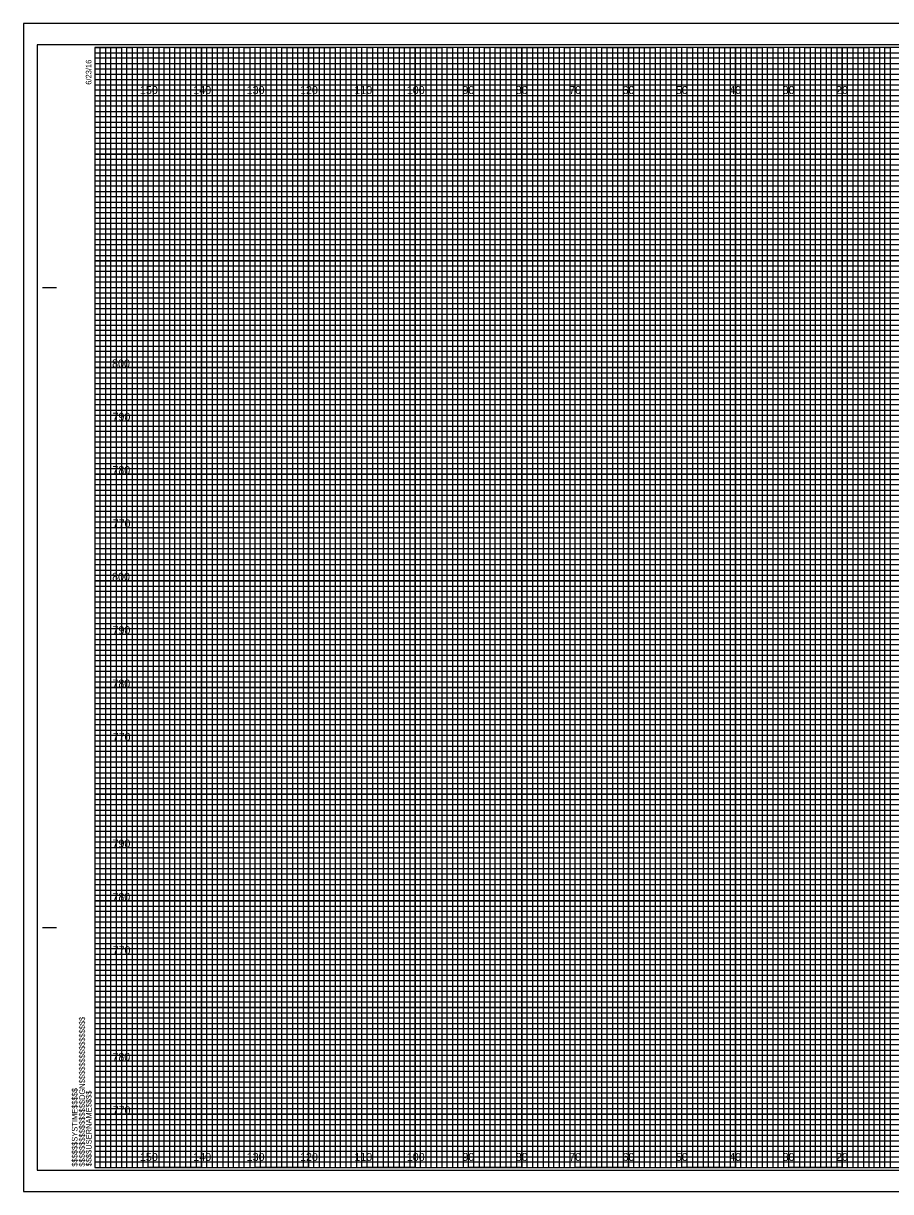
# Model space of a CAD drawing. Extents: x -13 to 323, y -4 to 214.
# Drawn here: x -13.4 to 149.1, y -4.5 to 214.5 of the extents above; entities that cross this region are included whole.
import ezdxf

# ---------------------------------------------------------------- set-up
doc = ezdxf.new("R2010")
doc.units = 0
for name, color, linetype in [('Exist Cross Section Cell', 7, 'Continuous'), ('Exist XS Center Line Elevation Label', 7, 'Continuous'), ('Exist XS Ground Line', 7, 'Continuous'), ('Prop CMT Conc Surface', 7, 'Continuous'), ('Prop CMT Concrete Structures', 7, 'Continuous'), ('Prop CMT Pvmt Course 1', 7, 'Continuous'), ('Prop CMT Pvmt Course 1 CG', 7, 'Continuous'), ('Prop CMT Pvmt Course 2', 7, 'Continuous'), ('Prop CMT Pvmt Surface', 7, 'Continuous'), ('Scratch_Level_1', 7, 'Continuous'), ('Scratch_Level_7', 7, 'Continuous')]:
    doc.layers.add(name, color=color, linetype=linetype)

msp = doc.modelspace()

# ---------------------------------------------------------------- linework, layer by layer
at = {"layer": 'Exist XS Center Line Elevation Label'}
for points in [[(0, 210), (5, 210), (5, 0), (15, 0), (15, 210), (25, 210), (25, 0), (35, 0), (35, 210), (45, 210), (45, 0), (55, 0), (55, 210), (65, 210), (65, 0), (75, 0), (75, 210), (85, 210), (85, 0), (95, 0), (95, 210), (105, 210), (105, 0), (115, 0), (115, 210), (125, 210), (125, 0), (135, 0), (135, 210), (145, 210), (145, 0), (155, 0)], [(0, 205), (275, 205)], [(0, 185), (320, 185), (320, 195), (0, 195)], [(0, 165), (320, 165), (320, 175), (0, 175)], [(0, 145), (320, 145), (320, 155), (0, 155)], [(0, 125), (320, 125), (320, 135), (0, 135)], [(0, 105), (320, 105), (320, 115), (0, 115)], [(0, 85), (320, 85), (320, 95), (0, 95)], [(0, 65), (320, 65), (320, 75), (0, 75)], [(0, 45), (320, 45), (320, 55), (0, 55)], [(0, 25), (320, 25), (320, 35), (0, 35)], [(0, 5), (320, 5), (320, 15), (0, 15)]]:
    msp.add_lwpolyline(points, dxfattribs=at)
at = {"layer": 'Exist XS Ground Line'}
for p, q in [((10, 210), (0, 210)), ((10, 0), (10, 210)), ((30, 210), (20, 210)), ((20, 210), (20, 0)), ((30, 0), (30, 210)), ((50, 210), (40, 210)), ((40, 210), (40, 0)), ((50, 0), (50, 210)), ((70, 210), (60, 210)), ((60, 210), (60, 0)), ((70, 0), (70, 210)), ((90, 210), (80, 210)), ((80, 210), (80, 0)), ((90, 0), (90, 210)), ((110, 210), (100, 210)), ((100, 210), (100, 0)), ((110, 0), (110, 210)), ((130, 210), (120, 210)), ((120, 210), (120, 0)), ((130, 0), (130, 210)), ((150, 210), (140, 210)), ((140, 210), (140, 0)), ((20, 0), (10, 0)), ((40, 0), (30, 0)), ((60, 0), (50, 0)), ((80, 0), (70, 0)), ((100, 0), (90, 0)), ((120, 0), (110, 0)), ((140, 0), (130, 0))]:
    msp.add_line(p, q, dxfattribs=at)
for points in [[(0, 200), (320, 200), (320, 190), (0, 190)], [(0, 180), (320, 180), (320, 170), (0, 170)], [(0, 160), (320, 160), (320, 150), (0, 150)], [(0, 140), (320, 140), (320, 130), (0, 130)], [(0, 120), (320, 120), (320, 110), (0, 110)], [(0, 100), (320, 100), (320, 90), (0, 90)], [(0, 80), (320, 80), (320, 70), (0, 70)], [(0, 60), (320, 60), (320, 50), (0, 50)], [(0, 40), (320, 40), (320, 30), (0, 30)], [(0, 20), (320, 20), (320, 10), (0, 10)]]:
    msp.add_lwpolyline(points, dxfattribs=at)
at = {"layer": 'Prop CMT Concrete Structures'}
msp.add_lwpolyline([(-13.4, -4.5), (323.3, -4.5), (323.3, 214.5), (-13.4, 214.5)], close=True, dxfattribs=at)
at = {"layer": 'Prop CMT Pvmt Course 1'}
for p, q in [((323.3, 214.5), (-13.4, 214.5)), ((-13.4, 214.5), (-13.4, -4.5)), ((-13.4, -4.5), (323.3, -4.5))]:
    msp.add_line(p, q, dxfattribs=at)
at = {"layer": 'Prop CMT Pvmt Course 1 CG'}
for p, q in [((10, 0), (10, 210)), ((20, 0), (20, 210)), ((30, 0), (30, 210)), ((40, 0), (40, 210)), ((50, 0), (50, 210)), ((60, 0), (60, 210)), ((70, 0), (70, 210)), ((80, 0), (80, 210)), ((90, 0), (90, 210)), ((100, 0), (100, 210)), ((110, 0), (110, 210)), ((120, 0), (120, 210)), ((130, 0), (130, 210)), ((140, 0), (140, 210)), ((0, 200), (320, 200)), ((0, 190), (320, 190)), ((0, 180), (320, 180)), ((0, 170), (320, 170)), ((0, 160), (320, 160)), ((0, 150), (320, 150)), ((0, 140), (320, 140)), ((0, 130), (320, 130)), ((0, 120), (320, 120)), ((0, 110), (320, 110)), ((0, 100), (320, 100)), ((0, 90), (320, 90)), ((0, 80), (320, 80)), ((0, 70), (320, 70)), ((0, 60), (320, 60)), ((0, 50), (320, 50)), ((0, 40), (320, 40)), ((0, 30), (320, 30)), ((0, 20), (320, 20)), ((0, 10), (320, 10))]:
    msp.add_line(p, q, dxfattribs=at)
at = {"layer": 'Prop CMT Pvmt Course 2'}
for points in [[(0, 0), (1, 0), (1, 210), (2, 210), (2, 0)], [(2, 0), (3, 0), (3, 210), (4, 210), (4, 0)], [(5, 0), (6, 0), (6, 210), (7, 210), (7, 0)], [(7, 0), (8, 0), (8, 210), (9, 210), (9, 0)], [(10, 0), (11, 0), (11, 210), (12, 210), (12, 0)], [(12, 0), (13, 0), (13, 210), (14, 210), (14, 0)], [(15, 0), (16, 0), (16, 210), (17, 210), (17, 0)], [(17, 0), (18, 0), (18, 210), (19, 210), (19, 0)], [(20, 0), (21, 0), (21, 210), (22, 210), (22, 0)], [(22, 0), (23, 0), (23, 210), (24, 210), (24, 0)], [(25, 0), (26, 0), (26, 210), (27, 210), (27, 0)], [(27, 0), (28, 0), (28, 210), (29, 210), (29, 0)], [(30, 0), (31, 0), (31, 210), (32, 210), (32, 0)], [(32, 0), (33, 0), (33, 210), (34, 210), (34, 0)], [(35, 0), (36, 0), (36, 210), (37, 210), (37, 0)], [(37, 0), (38, 0), (38, 210), (39, 210), (39, 0)], [(40, 0), (41, 0), (41, 210), (42, 210), (42, 0)], [(42, 0), (43, 0), (43, 210), (44, 210), (44, 0)], [(45, 0), (46, 0), (46, 210), (47, 210), (47, 0)], [(47, 0), (48, 0), (48, 210), (49, 210), (49, 0)], [(50, 0), (51, 0), (51, 210), (52, 210), (52, 0)], [(52, 0), (53, 0), (53, 210), (54, 210), (54, 0)], [(55, 0), (56, 0), (56, 210), (57, 210), (57, 0)], [(57, 0), (58, 0), (58, 210), (59, 210), (59, 0)], [(60, 0), (61, 0), (61, 210), (62, 210), (62, 0)], [(62, 0), (63, 0), (63, 210), (64, 210), (64, 0)], [(65, 0), (66, 0), (66, 210), (67, 210), (67, 0)], [(67, 0), (68, 0), (68, 210), (69, 210), (69, 0)], [(70, 0), (71, 0), (71, 210), (72, 210), (72, 0)], [(72, 0), (73, 0), (73, 210), (74, 210), (74, 0)], [(75, 0), (76, 0), (76, 210), (77, 210), (77, 0)], [(77, 0), (78, 0), (78, 210), (79, 210), (79, 0)], [(80, 0), (81, 0), (81, 210), (82, 210), (82, 0)], [(82, 0), (83, 0), (83, 210), (84, 210), (84, 0)], [(85, 0), (86, 0), (86, 210), (87, 210), (87, 0)], [(87, 0), (88, 0), (88, 210), (89, 210), (89, 0)], [(90, 0), (91, 0), (91, 210), (92, 210), (92, 0)], [(92, 0), (93, 0), (93, 210), (94, 210), (94, 0)], [(95, 0), (96, 0), (96, 210), (97, 210), (97, 0)], [(97, 0), (98, 0), (98, 210), (99, 210), (99, 0)], [(100, 0), (101, 0), (101, 210), (102, 210), (102, 0)], [(102, 0), (103, 0), (103, 210), (104, 210), (104, 0)], [(105, 0), (106, 0), (106, 210), (107, 210), (107, 0)], [(107, 0), (108, 0), (108, 210), (109, 210), (109, 0)], [(110, 0), (111, 0), (111, 210), (112, 210), (112, 0)], [(112, 0), (113, 0), (113, 210), (114, 210), (114, 0)], [(115, 0), (116, 0), (116, 210), (117, 210), (117, 0)], [(117, 0), (118, 0), (118, 210), (119, 210), (119, 0)], [(120, 0), (121, 0), (121, 210), (122, 210), (122, 0)], [(122, 0), (123, 0), (123, 210), (124, 210), (124, 0)], [(125, 0), (126, 0), (126, 210), (127, 210), (127, 0)], [(127, 0), (128, 0), (128, 210), (129, 210), (129, 0)], [(130, 0), (131, 0), (131, 210), (132, 210), (132, 0)], [(132, 0), (133, 0), (133, 210), (134, 210), (134, 0)], [(135, 0), (136, 0), (136, 210), (137, 210), (137, 0)], [(137, 0), (138, 0), (138, 210), (139, 210), (139, 0)], [(140, 0), (141, 0), (141, 210), (142, 210), (142, 0)], [(142, 0), (143, 0), (143, 210), (144, 210), (144, 0)], [(145, 0), (146, 0), (146, 210), (147, 210), (147, 0)], [(147, 0), (148, 0), (148, 210), (149, 210), (149, 0)]]:
    msp.add_lwpolyline(points, dxfattribs=at)
at = {"layer": 'Prop CMT Pvmt Surface'}
msp.add_lwpolyline([(-10.8, -0.5), (322.4, -0.5), (322.4, 210.5), (-10.8, 210.5)], close=True, dxfattribs=at)
at = {"layer": 'Scratch_Level_1'}
for p, q in [((0, 209), (260, 209)), ((260, 207.98), (0, 207.98)), ((0, 207.98), (0, 207)), ((0, 207), (260, 207)), ((260, 205.89), (0, 205.89)), ((0, 205.89), (0, 204)), ((0, 204), (320, 204))]:
    msp.add_line(p, q, dxfattribs=at)
for points in [[(0, 203), (270, 203), (320, 203), (320, 202), (0, 202)], [(0, 201), (320, 201), (320, 199), (0, 199)], [(0, 198), (320, 198), (320, 197), (0, 196.98)], [(0, 196), (320, 196), (320, 194), (0, 194)], [(0, 193), (320, 193), (320, 192), (0, 192)], [(0, 191), (320, 191), (320, 189), (0, 189)], [(0, 188), (320, 188), (320, 187), (0, 187)], [(0, 186), (320, 186), (320, 184), (0, 184)], [(0, 183), (320, 183), (320, 182), (0, 182)], [(0, 181), (320, 181), (320, 179), (0, 179)], [(0, 178), (320, 178), (320, 177), (0, 177)], [(0, 176), (320, 176), (320, 173.95), (320, 173), (320, 172), (0, 172)], [(0, 174), (320, 174), (320, 173), (0, 173)], [(0, 171), (320, 171), (320, 169), (0, 169.03)], [(0, 169.03), (320, 169), (320, 168), (0, 168)], [(0, 167), (320, 167), (320, 166), (0, 166)], [(0, 164), (320, 164), (320, 163), (0, 163)], [(0, 162), (320, 162), (320, 161), (0, 161)], [(-0.07, 158.89), (320, 158.89), (320, 157.88), (-0.07, 157.88)], [(0, 157), (320, 157), (320, 156), (0, 156)], [(0, 154), (320, 154), (320, 153), (0, 153)], [(0, 152), (320, 152), (320, 151), (0, 151)], [(0, 149), (320, 149), (320, 148), (0, 148)], [(0, 147), (320, 147), (320, 146), (0, 146)], [(0, 144), (320, 144), (320, 143), (0, 143)], [(0, 142), (320, 142), (320, 141), (0, 141)], [(0, 139), (320, 139), (319.99, 137.98), (0, 138)], [(0, 137), (320, 137), (320, 136), (0, 136)], [(0, 134), (320, 134), (320, 133), (0, 133)], [(0, 132), (320, 132), (320, 131), (0, 131)], [(0, 129), (320, 129), (320, 128), (0, 128)], [(0, 127), (320, 127), (320, 126), (0, 126)], [(0, 124), (320, 124), (320, 123), (0, 123)], [(0, 122), (320, 122), (320, 121), (0, 121)], [(0, 119), (320, 119), (320, 118), (0, 118)], [(0, 116.99), (320.07, 116.91), (320, 116), (0, 116)], [(0, 114), (320, 114), (320, 113), (0, 113)], [(0, 112), (320, 112), (320, 111), (0, 111)], [(0, 109), (320, 109), (320, 108), (0, 108)], [(0, 107), (320, 107), (320, 106), (0, 106)], [(0, 104), (320, 104), (320, 103), (0, 103)], [(0, 102), (320, 102), (320, 101), (0, 101)], [(0, 99), (320, 99), (320, 98), (0, 98)], [(0, 97), (320, 97), (320, 96), (0, 96)], [(0, 94), (320, 94), (320, 93), (0, 93)], [(0, 92), (320, 92), (320, 91), (0, 91)], [(0, 89), (320, 89), (320, 88), (0, 88)], [(0, 87), (320, 87), (320, 86), (0, 86)], [(0, 84), (320, 84), (320, 83), (0, 83)], [(0, 82), (320, 82), (320, 81), (0, 81)], [(0, 79), (320, 79), (319.99, 77.98), (0, 78)], [(0, 77), (320, 77), (320, 76), (0, 76)], [(0, 74), (320, 74), (320, 73), (0, 73)], [(0, 72), (320, 72), (320, 71), (0, 71)], [(0, 69), (320, 69), (320, 68), (0, 68)], [(0, 67), (320, 67), (320, 66), (0, 66)], [(0, 64), (320, 64), (320, 63), (0, 63)], [(0, 62), (320, 62), (320, 61), (0, 61)], [(0, 59), (320, 59), (320, 58), (0, 58)], [(0, 56.99), (320.07, 56.91), (320, 56), (0, 56)], [(0, 54), (320, 54), (320, 53), (0, 53)], [(0, 52), (320, 52), (320, 51), (0, 51)], [(0, 49), (320, 49), (320, 48), (0, 48)], [(0, 47), (320, 47), (320, 46), (0, 46)], [(0, 44), (320, 44), (320, 43), (0, 43)], [(0, 42), (320, 42), (320, 41), (0, 41)], [(0, 39), (320, 39), (320, 38), (0, 38)], [(0, 37), (320, 37), (320, 36), (0, 36)], [(0, 34), (320, 34), (320, 33), (0, 33)], [(0, 32), (320, 32), (320, 31), (0, 31)], [(0, 29), (320, 29), (320, 28), (0, 28)], [(0, 27), (320, 27), (320, 26), (0, 26)], [(0, 24), (320, 24), (320, 23), (0, 23)], [(0, 22), (320, 22), (320, 21), (0, 21)], [(0, 19), (320, 19), (320, 18), (0, 18)], [(0, 17), (320, 17), (320, 16), (0, 16)], [(0, 14), (320, 14), (320, 13), (0, 13)], [(0, 12), (320, 12), (320, 11), (0, 11)], [(0, 9), (320, 9), (320, 8), (0, 8)], [(0, 7), (320, 7), (320, 6), (0, 6)], [(0, 4), (320, 4), (320, 3), (0, 3)], [(0, 2), (320, 2), (320, 1), (0, 1)]]:
    msp.add_lwpolyline(points, dxfattribs=at)
at = {"layer": 'Scratch_Level_7'}
for p, q in [((-9.8, 165), (-7.3, 165)), ((-9.7, 165), (-7.2, 165)), ((-9.8, 45), (-7.3, 45)), ((-9.7, 45), (-7.2, 45)), ((0, 0), (0, 0)), ((0, 0), (0, 0)), ((0, 0), (0, 0)), ((0, 0), (0, 0)), ((0, 0), (0, 0)), ((0, 0), (0, 0)), ((0, 0), (0, 0))]:
    msp.add_line(p, q, dxfattribs=at)
msp.add_lwpolyline([(320, 210), (0, 210), (0, 0), (320, 0)], close=True, dxfattribs=at)

# ---------------------------------------------------------------- texts
at = {"layer": 'Exist Cross Section Cell'}
for s, p in [('150', (8.44, 201.25)), ('140', (18.44, 201.25)), ('130', (28.44, 201.25)), ('120', (38.44, 201.25)), ('110', (48.62, 201.25)), ('100', (58.44, 201.25)), ('90', (68.86, 201.25)), ('80', (78.86, 201.25)), ('70', (88.86, 201.25)), ('60', (98.86, 201.25)), ('50', (108.86, 201.25)), ('40', (118.86, 201.25)), ('30', (128.86, 201.25)), ('20', (138.86, 201.25)), ('150', (8.44, 1.25)), ('140', (18.44, 1.25)), ('130', (28.44, 1.25)), ('120', (38.44, 1.25)), ('110', (48.62, 1.25)), ('100', (58.44, 1.25)), ('90', (68.86, 1.25)), ('80', (78.86, 1.25)), ('70', (88.86, 1.25)), ('60', (98.86, 1.25)), ('50', (108.86, 1.25)), ('40', (118.86, 1.25)), ('30', (128.86, 1.25)), ('20', (138.86, 1.25))]:
    msp.add_text(s, height=1.5, dxfattribs=at).set_placement(p)
at = {"layer": 'Prop CMT Conc Surface'}
for s, p in [('800', (3.22, 150)), ('790', (3.3, 140)), ('780', (3.28, 130)), ('770', (3.33, 120)), ('800', (3.22, 110)), ('790', (3.3, 100)), ('780', (3.28, 90)), ('770', (3.33, 80)), ('790', (3.3, 60)), ('780', (3.28, 50)), ('770', (3.33, 40)), ('780', (3.28, 20)), ('770', (3.33, 10))]:
    msp.add_text(s, height=1.5, dxfattribs=at).set_placement(p)
at = {"layer": 'Scratch_Level_7'}
for s, p in [('6/23/16', (-0.65, 203)), ('$$$$$$$$$$$$$$$$DGN$$$$$$$$$$$$$$$$', (-1.88, 0.18)), ('$$$$$$SYSTIME$$$$$', (-3.26, 0.18)), ('$$$$USERNAME$$$$', (-0.62, 0.23))]:
    msp.add_text(s, height=1.05, rotation=90, dxfattribs=at).set_placement(p)

doc.saveas('drawing.dxf')
